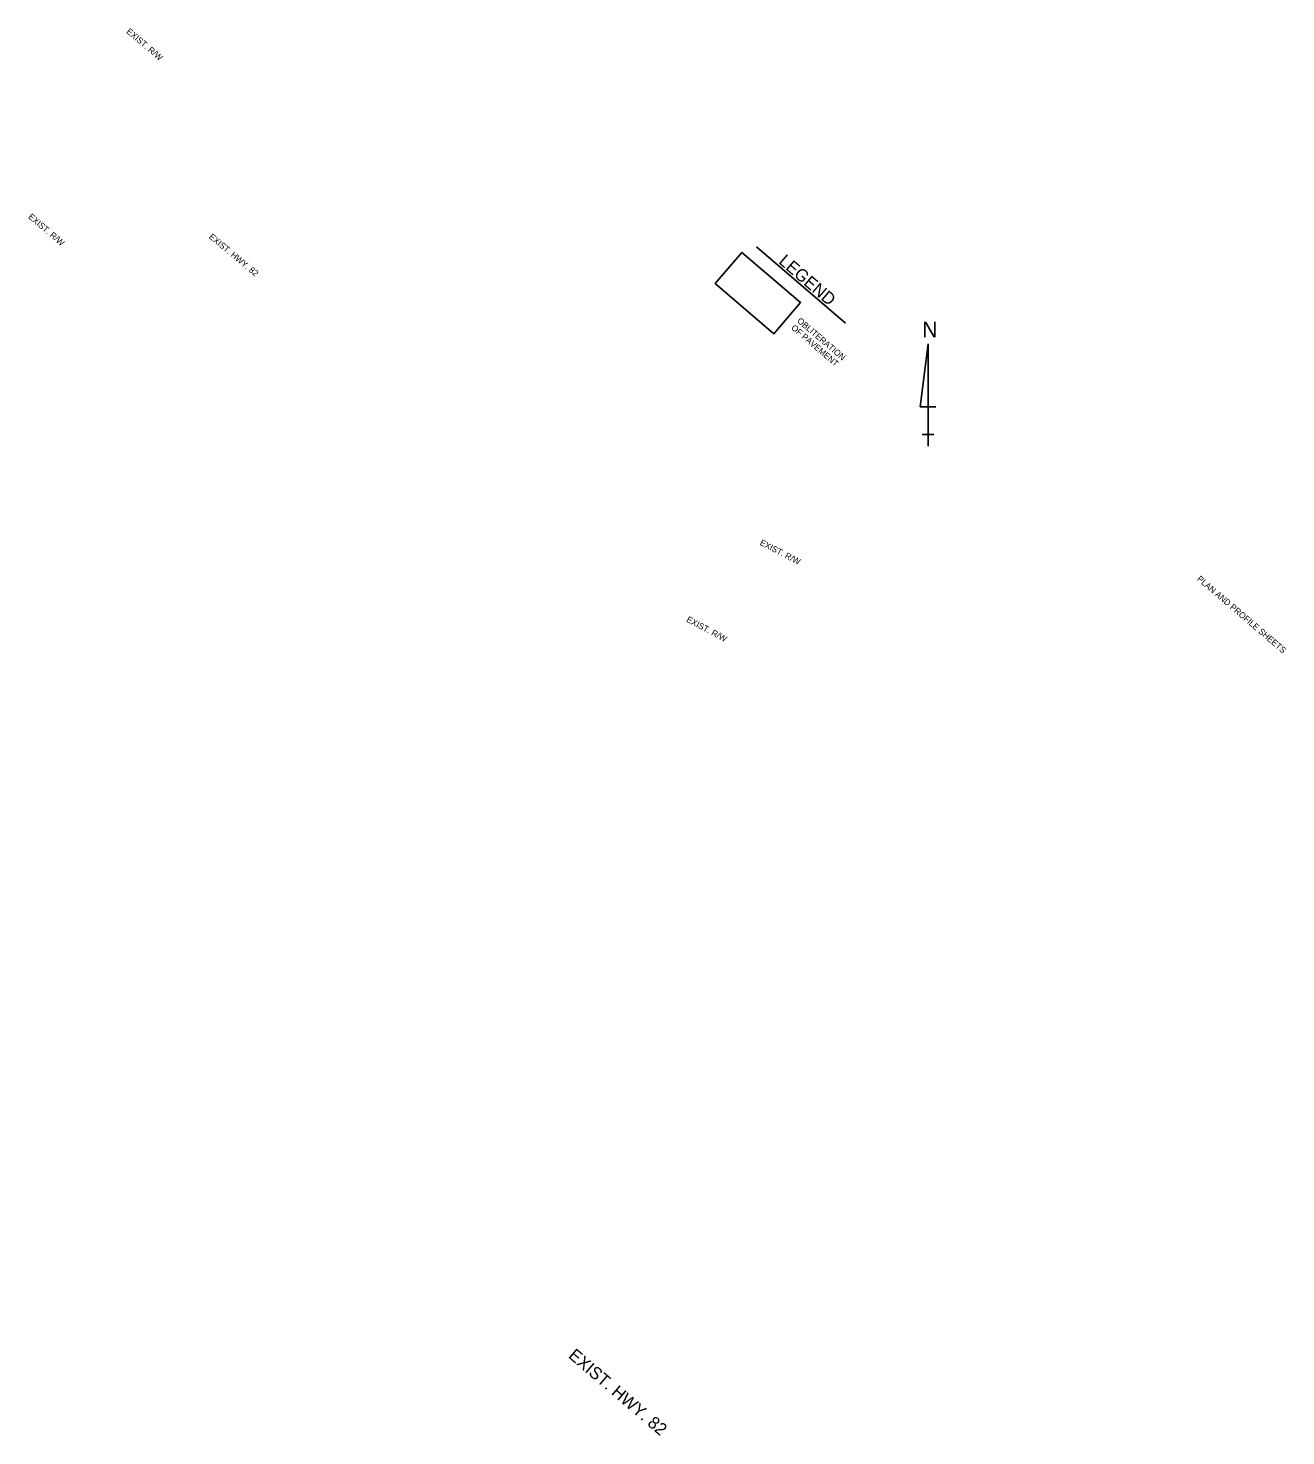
# Model space of a CAD drawing. Extents: x 884995 to 886225, y 1563968 to 1565344.
import ezdxf

# ---------------------------------------------------------------- set-up
doc = ezdxf.new("R2010")
doc.units = 0
for name, color, linetype in [('Default', 7, 'Continuous'), ('R_Annotation_Points', 7, 'Continuous'), ('R_Border', 7, 'Continuous'), ('R_Border Prem', 7, 'Continuous')]:
    doc.layers.add(name, color=color, linetype=linetype)

msp = doc.modelspace()

# ---------------------------------------------------------------- linework, layer by layer
at = {"layer": 'Default'}
for p, q in [((885874.8, 1565035.7), (885867.1, 1564974.1)), ((885874.8, 1564935.7), (885874.8, 1565035.7)), ((885874.8, 1565035.7), (885874.8, 1564958.7)), ((885867.1, 1564974.1), (885882.5, 1564974.1)), ((885874.8, 1564935.7), (885874.8, 1564958.7)), ((885874.8, 1564947.2), (885869, 1564947.2)), ((885869, 1564947.2), (885880.5, 1564947.2)), ((885874.8, 1564935.7), (885874.8, 1564947.2))]:
    msp.add_line(p, q, dxfattribs=at)
at = {"layer": 'R_Annotation_Points'}
msp.add_lwpolyline([(885666.7, 1565094.8), (885724.1, 1565045.6), (885750.1, 1565076), (885692.7, 1565125.1), (885666.7, 1565094.8)], dxfattribs=at)
at = {"layer": 'R_Border'}
msp.add_line((885706.9, 1565130.7), (885794, 1565056.1), dxfattribs=at)
msp.add_lwpolyline([(885666.7, 1565094.8), (885724.1, 1565045.6), (885750.1, 1565076), (885692.7, 1565125.1)], close=True, dxfattribs=at)

# ---------------------------------------------------------------- texts
at = {"layer": 'Default'}
msp.add_text('N', height=15.4, dxfattribs=at).set_placement((885869.1, 1565042.1))
at = {"layer": 'R_Border'}
for s, height, rotation, p in [('EXIST. R/W', 6, 319.4335, (885090.4, 1565340.2)), ('EXIST. R/W', 6, 319.4335, (884994.4, 1565159.1)), ('EXIST. HWY. 82', 6, 320.1268, (885171.1, 1565139.5)), ('LEGEND', 12, 319.4335, (885727.9, 1565115.1)), ('OF PAVEMENT', 6, 319.4335, (885740.4, 1565050.5)), ('OBLITERATION ', 6, 319.4335, (885746.2, 1565057.3)), ('EXIST. R/W', 6, 332.4651, (885709.7, 1564839.5)), ('EXIST. R/W', 6, 331.8951, (885637.9, 1564764.4)), ('EXIST. HWY. 82', 12, 319.4335, (885522.3, 1564045.3))]:
    msp.add_text(s, height=height, rotation=rotation, dxfattribs=at).set_placement(p)
at = {"layer": 'R_Border Prem'}
msp.add_text('PLAN AND PROFILE SHEETS', height=6, rotation=319.4335, dxfattribs=at).set_placement((886137.2, 1564805))

doc.saveas('drawing.dxf')
